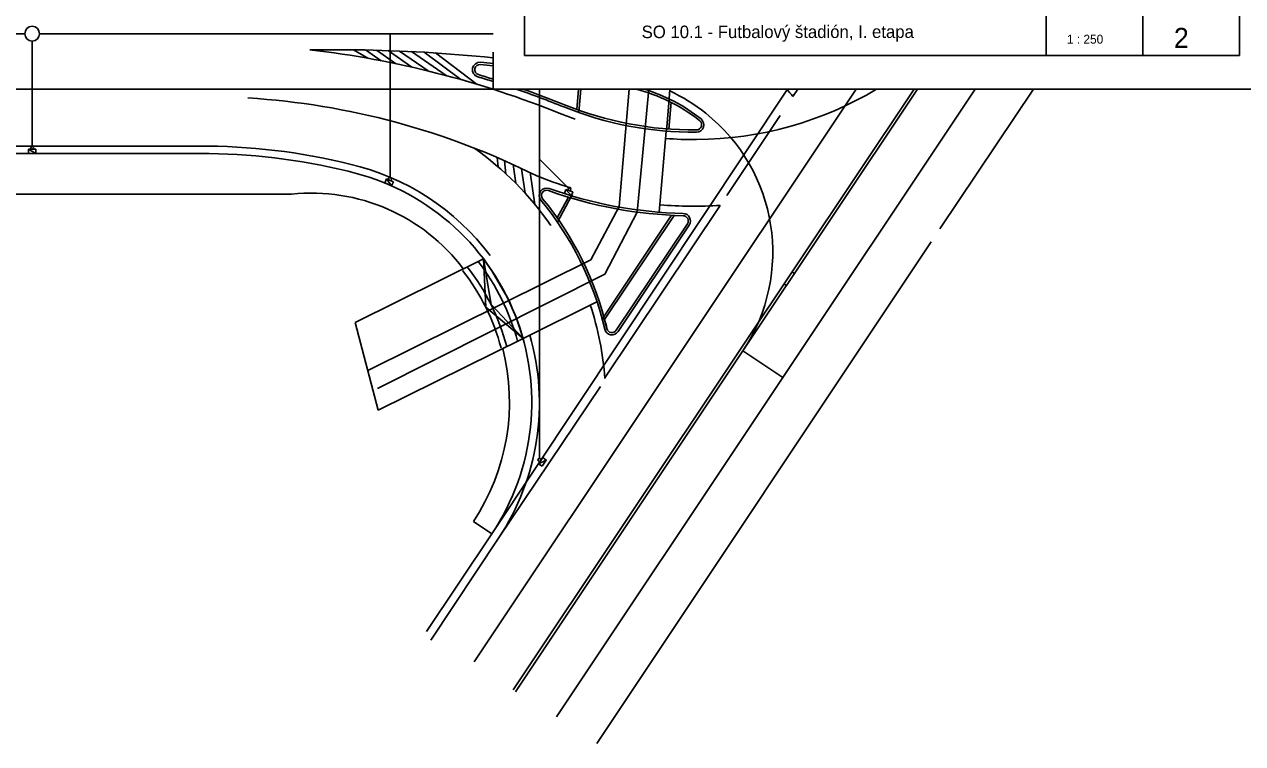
# Model space of a CAD drawing. Extents: x -264205 to -263659, y -1242401 to -1242060.
# Drawn here: x -263854.4 to -263772.2, y -1242352.1 to -1242303.5 of the extents above; entities that cross this region are included whole.
import ezdxf

# ---------------------------------------------------------------- set-up
doc = ezdxf.new("R2010")
doc.units = 0
for name, color, linetype in [('OBRUBNIKY_KOMUNIKACIE_PROJEKT', 7, 'Continuous'), ('RAM_NA_TLAC_12xA4_1-250', 7, 'Continuous'), ('ROZPISKA', 7, 'Continuous'), ('SITUACIA_DSP_2D', 7, 'Continuous'), ('TDZ_VODOROVNE_PROJEKT', 7, 'Continuous')]:
    doc.layers.add(name, color=color, linetype=linetype)

msp = doc.modelspace()

# ---------------------------------------------------------------- linework, layer by layer
at = {"layer": 'OBRUBNIKY_KOMUNIKACIE_PROJEKT'}
for p, q in [((-263817.028, -1242307.886), (-263817.145, -1242309.262)), ((-263816.877, -1242307.886), (-263817.012, -1242309.469)), ((-263810.912, -1242308.547), (-263811.097, -1242310.721)), ((-263810.781, -1242308.779), (-263810.935, -1242310.583)), ((-263842.601, -1242312.24), (-263924.192, -1242312.232)), ((-264038.443, -1242314.982), (-263836.403, -1242314.982)), ((-263818.469, -1242316.58), (-263817.711, -1242315.183)), ((-263818.453, -1242316.866), (-263817.491, -1242315.093)), ((-263810.751, -1242316.405), (-263815.43, -1242323.41)), ((-263810.576, -1242316.414), (-263815.268, -1242323.437)), ((-263809.676, -1242316.98), (-263814.48, -1242324.171)), ((-263809.551, -1242317.064), (-263814.356, -1242324.254)), ((-263823.444, -1242319.346), (-263832.112, -1242323.652)), ((-263823.444, -1242319.346), (-263832.112, -1242323.652)), ((-263823.444, -1242319.346), (-263823.288, -1242322.618)), ((-263822.869, -1242320.154), (-263823.444, -1242319.346)), ((-263821.84, -1242321.938), (-263822.869, -1242320.154)), ((-263813.542, -1242320.69), (-263813.542, -1242320.69)), ((-263802.615, -1242320.222), (-263802.448, -1242320.333)), ((-263803.16, -1242321.04), (-263802.993, -1242321.151)), ((-263823.288, -1242322.618), (-263820.775, -1242324.719)), ((-263821.24, -1242323.31), (-263821.84, -1242321.938)), ((-263820.775, -1242324.719), (-263821.24, -1242323.31)), ((-263832.112, -1242323.652), (-263830.544, -1242329.573)), ((-263832.112, -1242323.652), (-263830.544, -1242329.573)), ((-263820.775, -1242324.719), (-263830.544, -1242329.573)), ((-263830.544, -1242329.573), (-263820.775, -1242324.719)), ((-263824.127, -1242337.081), (-263822.88, -1242337.914)), ((-263827.28, -1242344.5), (-263822.88, -1242337.914))]:
    msp.add_line(p, q, dxfattribs=at)
for centre, radius, start, end in [((-263823.686, -1242306.574), 0.5, 84.50312, 253.37264), ((-263832, -1242392.966), 87.291, 83.94319, 84.50312), ((-263823.686, -1242306.574), 0.35, 84.50312, 253.37264), ((-263842.678, -1242370.168), 66.019, 72.46765, 73.37264), ((-263832, -1242392.966), 87.141, 83.93272, 84.50312), ((-263842.678, -1242370.168), 65.869, 72.42642, 73.37264), ((-263842.678, -1242370.168), 65.869, 68.01969, 71.00472), ((-263842.678, -1242370.168), 66.019, 68.01969, 70.6301), ((-263815.913, -1242318.902), 11.35, 51.49122, 76.06982), ((-263815.913, -1242318.902), 11.5, 51.49122, 73.32144), ((-263809.228, -1242287.295), 23.5, 248.01969, 270.4085), ((-263809.228, -1242287.295), 23.35, 248.01969, 270.4085), ((-263809.064, -1242310.295), 0.35, 270.4085, 51.49122), ((-263809.064, -1242310.295), 0.5, 270.4085, 51.49122), ((-263842.427, -1242353.351), 41.111, 76.13622, 90.24149), ((-263836.184, -1242329.025), 16, 326.2529, 76.96946), ((-263835.045, -1242327.715), 12.805, 36.92053, 96.08735), ((-263819.181, -1242315.066), 0.5, 70.28283, 219.38571), ((-263819.181, -1242315.066), 0.35, 70.28283, 219.38571), ((-263809.228, -1242287.295), 29.15, 250.28283, 268.56407), ((-263809.228, -1242287.295), 29, 250.28283, 268.56407), ((-263836.184, -1242329.025), 21.5, 13.26701, 39.38571), ((-263836.184, -1242329.025), 21.65, 13.26701, 39.38571), ((-263809.967, -1242316.786), 0.35, 326.2529, 88.56407), ((-263809.967, -1242316.786), 0.5, 326.2529, 88.56407), ((-263836.184, -1242329.025), 14.4, 14.72564, 38.11574), ((-263836.184, -1242329.025), 21.65, 13.26701, 14.95961), ((-263814.771, -1242323.977), 0.5, 193.26701, 326.2529), ((-263814.771, -1242323.977), 0.35, 193.26701, 326.2529), ((-263836.228, -1242329.021), 14.539, 326.33444, 14.41665)]:
    msp.add_arc(centre, radius, start, end, dxfattribs=at)
at = {"layer": 'RAM_NA_TLAC_12xA4_1-250'}
msp.add_line((-263822.79, -1242305.386), (-263822.79, -1242307.886), dxfattribs=at)
msp.add_lwpolyline([(-263980.29, -1242085.136), (-263770.29, -1242085.136), (-263770.29, -1242307.886), (-263980.29, -1242307.886)], close=True, dxfattribs=at)
at = {"layer": 'ROZPISKA'}
for p, q in [((-263820.678, -1242287.348), (-263820.679, -1242305.612)), ((-263772.412, -1242287.347), (-263772.411, -1242305.612)), ((-263785.456, -1242299.351), (-263785.457, -1242305.61)), ((-263778.934, -1242299.613), (-263778.932, -1242305.611)), ((-263820.679, -1242305.612), (-263772.411, -1242305.612))]:
    msp.add_line(p, q, dxfattribs=at)
at = {"layer": 'SITUACIA_DSP_2D'}
for p, q in [((-263854.415, -1242304.147), (-263903.413, -1242304.147)), ((-263822.79, -1242304.152), (-263853.415, -1242304.148)), ((-263829.755, -1242313.856), (-263829.755, -1242304.151)), ((-263853.915, -1242311.749), (-263853.915, -1242304.647)), ((-263822.88, -1242337.914), (-263802.921, -1242307.886)), ((-263819.667, -1242332.824), (-263819.667, -1242307.886)), ((-263817.028, -1242307.886), (-263817.145, -1242309.262)), ((-263816.877, -1242307.886), (-263817.012, -1242309.468)), ((-263810.912, -1242308.547), (-263811.097, -1242310.721)), ((-263810.781, -1242308.779), (-263810.935, -1242310.583)), ((-263854.165, -1242311.949), (-263853.665, -1242311.949)), ((-263854.165, -1242312.239), (-263854.165, -1242311.949)), ((-263854.165, -1242311.949), (-263853.665, -1242312.239)), ((-263854.165, -1242311.949), (-263853.665, -1242312.239)), ((-263853.665, -1242311.949), (-263854.165, -1242311.949)), ((-263853.665, -1242311.949), (-263853.665, -1242312.239)), ((-263853.665, -1242312.239), (-263853.665, -1242311.949)), ((-263842.601, -1242312.24), (-263924.192, -1242312.232)), ((-263853.665, -1242312.239), (-263854.165, -1242312.239)), ((-263817.708, -1242314.574), (-263819.667, -1242312.615)), ((-263830.101, -1242314.219), (-263829.983, -1242313.954)), ((-263829.983, -1242313.954), (-263830.101, -1242314.219)), ((-263829.645, -1242314.423), (-263830.101, -1242314.219)), ((-263830.101, -1242314.219), (-263829.645, -1242314.423)), ((-263829.983, -1242313.954), (-263829.527, -1242314.158)), ((-263829.645, -1242314.423), (-263829.983, -1242313.954)), ((-263829.645, -1242314.423), (-263829.983, -1242313.954)), ((-263829.527, -1242314.158), (-263829.645, -1242314.423)), ((-264038.443, -1242314.982), (-263836.403, -1242314.982)), ((-263818.469, -1242316.58), (-263817.711, -1242315.183)), ((-263818.453, -1242316.866), (-263817.491, -1242315.093)), ((-263817.966, -1242314.94), (-263817.874, -1242314.665)), ((-263817.874, -1242314.665), (-263817.966, -1242314.94)), ((-263817.492, -1242315.099), (-263817.966, -1242314.94)), ((-263817.966, -1242314.94), (-263817.492, -1242315.099)), ((-263817.874, -1242314.665), (-263817.4, -1242314.824)), ((-263817.492, -1242315.099), (-263817.874, -1242314.665)), ((-263817.492, -1242315.099), (-263817.874, -1242314.665)), ((-263817.4, -1242314.824), (-263817.492, -1242315.099)), ((-263810.751, -1242316.405), (-263815.43, -1242323.41)), ((-263810.576, -1242316.414), (-263815.268, -1242323.437)), ((-263809.676, -1242316.98), (-263814.48, -1242324.171)), ((-263809.551, -1242317.064), (-263814.356, -1242324.254)), ((-263823.444, -1242319.346), (-263832.112, -1242323.652)), ((-263823.444, -1242319.346), (-263832.112, -1242323.652)), ((-263823.444, -1242319.346), (-263822.93, -1242322.44)), ((-263822.869, -1242320.154), (-263823.444, -1242319.346)), ((-263821.84, -1242321.938), (-263822.869, -1242320.154)), ((-263813.542, -1242320.69), (-263813.542, -1242320.69)), ((-263813.542, -1242320.69), (-263813.542, -1242320.69)), ((-263822.93, -1242322.44), (-263820.775, -1242324.719)), ((-263821.24, -1242323.31), (-263821.84, -1242321.938)), ((-263820.775, -1242324.719), (-263821.24, -1242323.31)), ((-263832.112, -1242323.652), (-263830.544, -1242329.573)), ((-263832.112, -1242323.652), (-263830.544, -1242329.573)), ((-263820.775, -1242324.719), (-263830.544, -1242329.573)), ((-263830.544, -1242329.573), (-263820.775, -1242324.719)), ((-263819.723, -1242333.187), (-263819.444, -1242332.772)), ((-263819.723, -1242333.187), (-263819.203, -1242332.933)), ((-263819.482, -1242333.349), (-263819.723, -1242333.187)), ((-263819.203, -1242332.933), (-263819.482, -1242333.349)), ((-263819.444, -1242332.772), (-263819.203, -1242332.933)), ((-263824.127, -1242337.081), (-263822.88, -1242337.914)), ((-263827.28, -1242344.5), (-263822.88, -1242337.914))]:
    msp.add_line(p, q, dxfattribs=at)
msp.add_lwpolyline([(-263819.723, -1242333.187), (-263819.203, -1242332.933), (-263819.444, -1242332.772)], close=True, dxfattribs=at)
for centre, radius in [((-263853.915, -1242304.147), 0.5), ((-263853.915, -1242311.849), 0.1), ((-263829.755, -1242313.956), 0.1), ((-263817.637, -1242314.644), 0.1), ((-263819.667, -1242332.924), 0.1)]:
    msp.add_circle(centre, radius, dxfattribs=at)
for centre, radius, start, end in [((-263823.686, -1242306.574), 0.5, 84.50312, 253.37264), ((-263832, -1242392.966), 87.291, 83.94316, 84.50312), ((-263823.686, -1242306.574), 0.35, 84.50312, 253.37264), ((-263842.678, -1242370.168), 66.019, 72.46762, 73.37264), ((-263832, -1242392.966), 87.141, 83.9327, 84.50312), ((-263842.678, -1242370.168), 65.869, 72.42639, 73.37264), ((-263842.678, -1242370.168), 65.869, 68.01969, 71.00464), ((-263842.678, -1242370.168), 66.019, 68.01969, 70.63003), ((-263815.913, -1242318.902), 11.35, 51.49122, 76.06913), ((-263815.913, -1242318.902), 11.5, 51.49122, 73.32086), ((-263809.228, -1242287.295), 23.5, 248.01969, 270.4085), ((-263809.228, -1242287.295), 23.35, 248.01969, 270.4085), ((-263809.064, -1242310.295), 0.35, 270.4085, 51.49122), ((-263809.064, -1242310.295), 0.5, 270.4085, 51.49122), ((-263842.427, -1242353.351), 41.111, 76.13622, 90.24149), ((-263836.184, -1242329.025), 16, 326.2529, 76.96946), ((-263835.045, -1242327.715), 12.805, 36.92053, 96.08735), ((-263819.181, -1242315.066), 0.5, 70.28283, 219.38571), ((-263819.181, -1242315.066), 0.35, 70.28283, 219.38571), ((-263809.228, -1242287.295), 29.15, 250.28283, 268.56407), ((-263809.228, -1242287.295), 29, 250.28283, 268.56407), ((-263836.184, -1242329.025), 21.5, 13.26701, 39.38571), ((-263836.184, -1242329.025), 21.65, 13.26701, 39.38571), ((-263809.967, -1242316.786), 0.35, 326.2529, 88.56407), ((-263809.967, -1242316.786), 0.5, 326.2529, 88.56407), ((-263836.184, -1242329.025), 14.8, 14.72564, 38.11574), ((-263836.184, -1242329.025), 15.6, 15.3332, 37.50818), ((-263836.184, -1242329.025), 21.65, 13.26701, 14.95961), ((-263814.771, -1242323.977), 0.5, 193.26701, 326.2529), ((-263814.771, -1242323.977), 0.35, 193.26701, 326.2529), ((-263836.228, -1242329.021), 14.539, 326.33444, 14.41665)]:
    msp.add_arc(centre, radius, start, end, dxfattribs=at)
at = {"layer": 'TDZ_VODOROVNE_PROJEKT'}
for p, q in [((-263832.039, -1242305.232), (-263835.165, -1242305.232)), ((-263832.216, -1242305.232), (-263831.251, -1242305.806)), ((-263831.408, -1242305.243), (-263830.341, -1242305.974)), ((-263830.671, -1242305.261), (-263829.376, -1242306.167)), ((-263829.878, -1242305.286), (-263828.277, -1242306.405)), ((-263829.11, -1242305.316), (-263827.186, -1242306.661)), ((-263828.303, -1242305.354), (-263825.963, -1242306.972)), ((-263827.448, -1242305.4), (-263824.977, -1242307.241)), ((-263826.672, -1242305.448), (-263823.87, -1242307.573)), ((-263824.083, -1242346.553), (-263798.276, -1242307.886)), ((-263818.504, -1242350.278), (-263790.25, -1242307.886)), ((-263814.291, -1242315.804), (-263813.616, -1242307.886)), ((-263813.062, -1242316.188), (-263812.288, -1242307.886)), ((-263810.915, -1242308.545), (-263810.858, -1242307.886)), ((-263794.371, -1242307.886), (-263806.091, -1242325.442)), ((-263794.13, -1242307.886), (-263805.925, -1242325.553)), ((-263802.223, -1242307.886), (-263802.558, -1242308.383)), ((-263786.319, -1242307.886), (-263792.626, -1242317.328)), ((-263807.021, -1242315.081), (-263803.412, -1242309.66)), ((-263811.571, -1242316.2), (-263811.101, -1242310.72)), ((-263842.661, -1242311.732), (-263980.94, -1242311.732)), ((-263822.515, -1242312.506), (-263822.452, -1242313.137)), ((-263822.025, -1242312.72), (-263821.925, -1242313.608)), ((-263821.448, -1242312.98), (-263821.265, -1242314.247)), ((-263820.866, -1242313.273), (-263820.628, -1242314.918)), ((-263820.29, -1242313.528), (-263819.981, -1242315.667)), ((-263816.19, -1242319.41), (-263814.291, -1242315.804)), ((-263815.248, -1242327.389), (-263807.46, -1242315.74)), ((-263815.26, -1242320.378), (-263813.062, -1242316.188)), ((-263815.8, -1242352.081), (-263793.213, -1242318.207)), ((-263831.211, -1242326.873), (-263816.19, -1242319.41)), ((-263830.6, -1242328.105), (-263815.26, -1242320.378)), ((-263815.783, -1242322.239), (-263820.775, -1242324.719)), ((-263821.435, -1242348.441), (-263806.091, -1242325.442)), ((-263821.286, -1242348.578), (-263805.925, -1242325.553)), ((-263805.925, -1242325.553), (-263803.224, -1242327.353)), ((-263822.425, -1242338.218), (-263815.553, -1242327.973)), ((-263822.425, -1242338.218), (-263827.003, -1242345.095))]:
    msp.add_line(p, q, dxfattribs=at)
for centre, radius, start, end in [((-263842.678, -1242370.168), 65.369, 68.01969, 83.40081), ((-263833.602, -1242410.935), 105.714, 84.12959, 89.15278), ((-263842.518, -1242358.966), 50.583, 63.43291, 86.40224), ((-263815.913, -1242318.902), 12, 51.49122, 65.14678), ((-263809.228, -1242287.295), 24, 270.4085, 300.91254), ((-263815.913, -1242318.902), 17, 38.22666, 40.39171), ((-263809.228, -1242287.295), 24, 248.01969, 250.45738), ((-263815.913, -1242318.902), 12, 326.34085, 51.49122), ((-263842.485, -1242353.555), 41.823, 76.13622, 90.24149), ((-263836.184, -1242329.025), 21, 34.6339, 54.82374), ((-263809.228, -1242287.295), 24, 265.42107, 270.4085), ((-263836.225, -1242329.073), 16.555, 36.94624, 76.86936), ((-263809.228, -1242287.295), 28.5, 248.01969, 253.02566), ((-263809.228, -1242287.295), 28.5, 265.37106, 273.55623), ((-263836.184, -1242329.025), 21, 4.34908, 18.20748), ((-263836.225, -1242329.073), 16.555, 326.46684, 16.06545)]:
    msp.add_arc(centre, radius, start, end, dxfattribs=at)

# ---------------------------------------------------------------- texts
at = {"layer": 'ROZPISKA'}
msp.add_text('SO 10.1 - Futbalový štadión, I. etapa', height=0.84385, rotation=0.04559, dxfattribs=at).set_placement((-263812.765, -1242304.445))
for s, height, p in [('2', 1.352, (-263776.829, -1242305.103)), ('1 : 250', 0.6008, (-263784.055, -1242304.817))]:
    msp.add_text(s, height=height, dxfattribs=at).set_placement(p)

doc.saveas('drawing.dxf')
